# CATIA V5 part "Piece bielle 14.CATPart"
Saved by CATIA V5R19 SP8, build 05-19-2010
Part number: Piece bielle 14
Bounding box of the stored display mesh (mm): x -2.927 to 42.927, y 64.03 to 92.97, z 6 to 12
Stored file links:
  G:\EU_thinkMotion\CFAO_2010\MMS_groupe3\MMS_groupe3\A reprendre\lpastor\lpastor\Piece bielle 14.CATPart
  C:\Users\Loïc\Documents\IFMA\Cours 2A\CFAO\Thinkmotion\Fourche avant.CATProduct
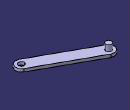
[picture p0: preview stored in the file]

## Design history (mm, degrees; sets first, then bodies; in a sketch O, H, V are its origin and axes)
Set1
  Plane1: linked copy from another document
  Line1 "Droite A (bielle 14)": linked copy from another document
  Line2 "Droite D (bielle 14)": linked copy from another document
  Plane2: linked copy from another document
Body1 (main body)
  Sketch1 on Plane1, origin (0, 0, 6), H (1, 0, 0), V (0, 1, 0)
    construction line L1 (1, 89) -> (39, 68)
    point P1 (1, 89)
    point P2 (39, 68)
    line L2 (2.9347, 92.501) -> (40.9347, 71.501)
    line L3 (37.0653, 64.499) -> (-0.9347, 85.499)
    arc A1 centre (39, 68) radius 4 from (40.9347, 71.501) to (37.0653, 64.499) cw
    arc A2 centre (1, 89) radius 4 from (-0.9347, 85.499) to (2.9347, 92.501) cw
    reference projected point E1 (39, 68) from Line1
    reference projected point E2 (1, 89) from Line2
    circle A3 centre (39, 68) radius 2
    point P7 (39, 68)
    reference projected point E3 (39, 68) from Line1
    distance L1 L2 = 4
    radius A3 = 2
    tangency: A1 L2, A2 L2, A1 L3, A2 L3
    coincidence: P2 E1, P1 E2, P7 E3
  Pad1: profile Sketch1, direction (0, 0, 1), up to Plane2
  Sketch2 on Plane2, origin (0, 0, 8), H (1, 0, 0), V (0, 1, 0)
    circle A1 centre (1, 89) radius 2
    point P1 (1, 89)
    reference projected point E1 (1, 89) from Line2
    radius A1 = 2
    coincidence: P1 E1
  Pad2: profile Sketch2, direction (0, 0, 1), length 4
